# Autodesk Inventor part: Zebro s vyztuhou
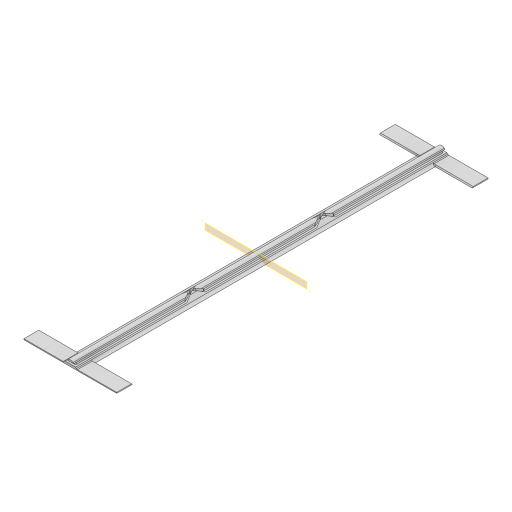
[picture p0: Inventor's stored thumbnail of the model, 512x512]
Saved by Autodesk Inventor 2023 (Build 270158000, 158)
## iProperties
Created: 2025-03
Part Number: Zebro s vyztuhou
Material: Všeobecné
Document SubType Name: Modeling
Designer: tomik
Density: 1 g/cm^3
Appearance: Výchozí
Author: tomik
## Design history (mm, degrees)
sketch "Náčrt1"
  geometry: L1 (0, 0)-(0, 11.016); L2 (0, 0)-(4, 0); L3 (0, 4)-(4, 0); L4 (0, 4)-(-4, 0); L5 (0, 0)-(-4, 0)
  constraints: 10 end point, 1 horizontal, 1 point on line, 1 symmetric about line, 1 vertical
  dimensions: "d0" = 4 distance of L1.start L2.end; "d1" = 4 distance from line of L3.start L2
extrude "Vysunutí1" new body sketch "Náčrt1" distance "d2" = 200; taper "d3" = 0 deg
sketch "Náčrt2"
  geometry: L1 (0, 0)-(9.652, 0); L2 (4, 0)-(0, 4) reference; L3 (4, 0)-(5.036, 0); A1 r 2.5 centre (5.036, 2.5) between (3.268, 0.732) and (5.036, 0)
  constraints: 4 end point, 3 tangent, 2 point on circle, 2 point on line, 1 centre point, 1 collinear, 1 horizontal
  dimensions: "d4" = 5 diameter of A1
extrude "Vysunutí2" join sketch "Náčrt2" distance "d5" = 200; taper "d6" = 0 deg
fillet "Zaoblení1" dims "d7" = 2
mirror "Zrcadlit1"
sketch "Náčrt3"
  geometry: L1 (-2.8, 1.2)-(-1.8, 1.2); L2 (-1.8, 1.2)-(-1.8, 2.2); L3 (-1.8, 2.2)-(-2.8, 2.2); L4 (-2.8, 2.2)-(-2.8, 1.2); L5 (0, 0)-(-6.364, 0); L6 (0, 0)-(0, 0.195); L7 (0, 0)-(0, 0.195); L8 (0, 0)-(0, 4.884); L9 (-1.8, 1.2)-(0, 1.2)
  constraints: 18 end point, 2 horizontal, 2 parallel, 2 perpendicular, 1 collinear, 1 point on line, 1 vertical
  dimensions: "d8" = 1.2 distance between parallel lines of L1 L5; "d9" = 1.8 distance between parallel lines of L2 L8; "d10" = 1 distance between parallel lines of L2 L4; "d11" = 1 distance between parallel lines of L3 L1
extrude "Vysunutí3" cut sketch "Náčrt3" distance "d12" = 60; taper "d13" = 0 deg
sketch "Náčrt4"
  geometry: L1 (1.8, 2.2)-(1.8, 1.2) reference; L2 (1.8, 1.2)-(2.8, 1.2) reference; L3 (1.414, 2.586)-(3.268, 0.732) reference; 1 further point
extrude "Vysunutí4" cut sketch "Náčrt4" distance "d14" = 60; taper "d15" = 0 deg
node "Pracovní rovina1"
sketch "Náčrt7"
  geometry: L1 (2.8, 1.2)-(1.8, 2.2) reference; L2 (1.8, 2.2)-(1.8, 1.2) reference; L3 (1.8, 1.2)-(2.8, 1.2) reference; 1 further point
extrude "Vysunutí6" cut sketch "Náčrt7" distance "d19" = 60; taper "d20" = 0 deg
mirror "Zrcadlit2"
node "Pracovní rovina3"
sketch "Náčrt8"
  geometry: L1 (-2.236, 60)-(-3.236, 60) reference; L2 (2.014, 70)-(-12.085, 70) reference; L3 (-3.236, 60)-(-3.236, 0) reference; L4 (-7.836, 70)-(-6.836, 70) reference; L5 (-3.236, 60)-(-7.836, 70); L6 (-2.236, 0)-(-2.236, 60) reference; L7 (-6.836, 70)-(-2.236, 60); 1 further point
  constraints: 4 end point
extrude "Vysunutí7" cut sketch "Náčrt8" stored distance "d22" = 60; taper "d23" = 0 deg
mirror "Zrcadlit3"
node "Pracovní rovina4"
mirror "Zrcadlit4"
fillet "Zaoblení2" dims "d25" = 0.5
sketch "Náčrt9"
  geometry: L1 (60, -1)-(0, -1) reference; L2 (59.891, 0)-(0, 0) reference; L3 (0, -1)-(1, -1); L4 (1, -1)-(1, 0); L5 (1, 0)-(0, 0); L6 (0, 0)-(0, -1); 3 further points
  constraints: 8 end point, 2 parallel, 1 horizontal, 1 perpendicular, 1 point on line
  dimensions: "d26" = 1 distance between parallel lines of L6 L4
extrude "Vysunutí8" cut sketch "Náčrt9" stored distance "d27" = 10; taper "d28" = 0 deg
fillet "Zaoblení3" dims "d29" = 0.5
mirror "Zrcadlit5"
sketch "Náčrt10"
  geometry: L1 (-5.036, 0)-(19.964, 0); L2 (19.964, 0)-(19.964, 8.5); L3 (19.964, 8.5)-(-5.036, 8.5); L4 (-5.036, 8.5)-(-5.036, 0); L5 (-30.036, 8.5)-(-5.036, 8.5); L6 (-30.036, 0)-(-30.036, 8.5); L7 (-5.036, 0)-(-30.036, 0); 1 further point
  constraints: 14 end point, 2 parallel, 2 symmetric about line, 1 horizontal, 1 midpoint, 1 perpendicular
  dimensions: "d30" = 25 distance between parallel lines of L4 L2; "d31" = 8.5 distance from line of point (7.464, 8.5) L1
extrude "Vysunutí9" join sketch "Náčrt10" distance "d32" = 0.5; taper "d33" = 0 deg
fillet "Zaoblení4" dims "d34" = 0.8
chamfer "Zkosení1" distance "d35" = 0.5; stored, may be unused: second distance "d36" = 2, angle "d37" = 45 deg
node "Pracovní rovina5"
mirror "Zrcadlit6"
node "Těleso1"
node "Pracovní rovina2"
